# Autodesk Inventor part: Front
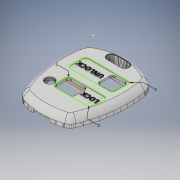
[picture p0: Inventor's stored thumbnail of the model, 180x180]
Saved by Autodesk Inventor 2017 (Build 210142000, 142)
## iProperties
Created: 2017-04
Part Number: Front
Material: Generic
Document SubType Name: Modeling
Designer: turin
Density: 1 g/cm^3
Appearance: Default
Author: turin
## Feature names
1. Extrusion1
2. Sweep1
3. Extrusion2
4. Extrusion3
5. Extrusion4
6. Base1
## Parameters: d0 = 0.5 mm, d1 = 0.5 mm, d3 = 0, d4 = 15 mm, d5 = 0, d6 = 0, d7 = 0.6 mm, d8 = 0, d17 = 2 mm, d19 = 2 mm, d20 = 2 mm, d21 = 0.4 mm, d22 = 0, d23 = 0.4 mm, d24 = 0
